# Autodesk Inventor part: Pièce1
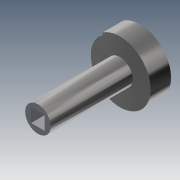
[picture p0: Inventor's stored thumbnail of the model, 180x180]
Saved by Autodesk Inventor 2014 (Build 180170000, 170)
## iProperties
Created: 2016-07
Part Number: Pièce1
Material: Générique
Document SubType Name: Modeling
Designer: shahh
Density: 1 g/cm^3
Appearance: Par défaut
Author: shahh
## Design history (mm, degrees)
sketch "Esquisse1"
  geometry: C1 r 7.5 at (0, 0); 1 further point
  constraints: 1 centre point, 1 coincident
  dimensions: "d0" = 15 diameter of C1
extrude "Extrusion1" new body sketch "Esquisse1" distance "d1" = 48; taper "d2" = 0 deg
sketch "Esquisse2"
  geometry: C1 r 7.5 at (0, 0) reference; C2 r 17 at (0, 0)
  constraints: 1 centre point, 1 coincident
  dimensions: "d3" = 34 diameter of C2
extrude "Extrusion2" join sketch "Esquisse2" distance "d4" = 2; taper "d5" = 0 deg
sketch "Esquisse3"
  geometry: C1 r 17 at (0, 0) reference; C2 r 16.5 at (0, 0)
  constraints: 1 centre point, 1 coincident
  dimensions: "d6" = 33 diameter of C2
extrude "Extrusion3" join sketch "Esquisse3" distance "d7" = 1; taper "d8" = 0 deg
sketch "Esquisse4"
  geometry: C1 r 7.5 at (0, 0) reference
extrude "Extrusion4" join sketch "Esquisse4" distance "d9" = 5; taper "d10" = 0 deg
sketch "Esquisse5"
  geometry: C1 r 7.5 at (0, 0) reference; C2 r 4 at (0, 0)
  constraints: 1 centre point, 1 coincident
  dimensions: "d11" = 8 diameter of C2
extrude "Extrusion5" join sketch "Esquisse5" distance "d12" = 7; taper "d13" = 0 deg
sketch "Esquisse6"
  geometry: L1 (4, 4)-(-4, 4); L2 (-4, 4)-(-4, -4); L3 (-4, -4)-(4, -4); L4 (4, -4)-(4, 4); C1 r 7.5 at (0, 0) reference
  constraints: 8 end point, 2 parallel, 1 horizontal, 1 perpendicular
  dimensions: "d14" = 8 distance of L1.start L1.end; "d15" = 4 distance from line of L2 C1.centre; "d16" = 4 distance from line of L3 C1.centre; "d17" = 4 distance from line of C1.centre L1
extrude "Extrusion6" cut sketch "Esquisse6" distance "d18" = 20; taper "d19" = 0 deg
sketch "Esquisse8"
  geometry: L1 (-10, 13.748)-(-10, 13.124); L2 (-10, -13.124)-(-10, -13.748); L3 (-10, 13.124)-(-10, 14.967); L4 (-10, -13.748)-(-10, -14.967); A1 r 16.5 centre (0, 0) between (-10, 13.124) and (-10, -13.124) reference; A2 r 17 centre (0, 0) between (-10, 13.748) and (-10, -13.748) reference; A3 r 18 centre (0, 0) between (-10, 14.967) and (-10, -14.967)
  constraints: 8 end point, 7 point on circle, 3 collinear, 1 centre point, 1 coincident, 1 vertical
  dimensions: "d25" = 10 distance from line of A1.centre L1; "d26" = 10 horizontal distance of A1.centre L2.end; "d27" = 1 radial gap between concentric circles of A3 A2
extrude "Extrusion7" join sketch "Esquisse8" distance "d28" = 9; taper "d29" = 0 deg
sketch "Esquisse9"
  geometry: L1 (-10, -14.967)-(-10, -13.748) reference; L2 (-10, 13.748)-(-10, 14.967) reference; A1 r 17 centre (0, 0) between (-10, -13.748) and (-10, 13.748) reference; A2 r 18 centre (0, 0) between (-10, -14.967) and (-10, 14.967) reference
extrude "Extrusion8" join sketch "Esquisse9" distance "d30" = 3; taper "d31" = 0 deg
fillet "Congé1" dims "d32" = 1
node "Solide1"
